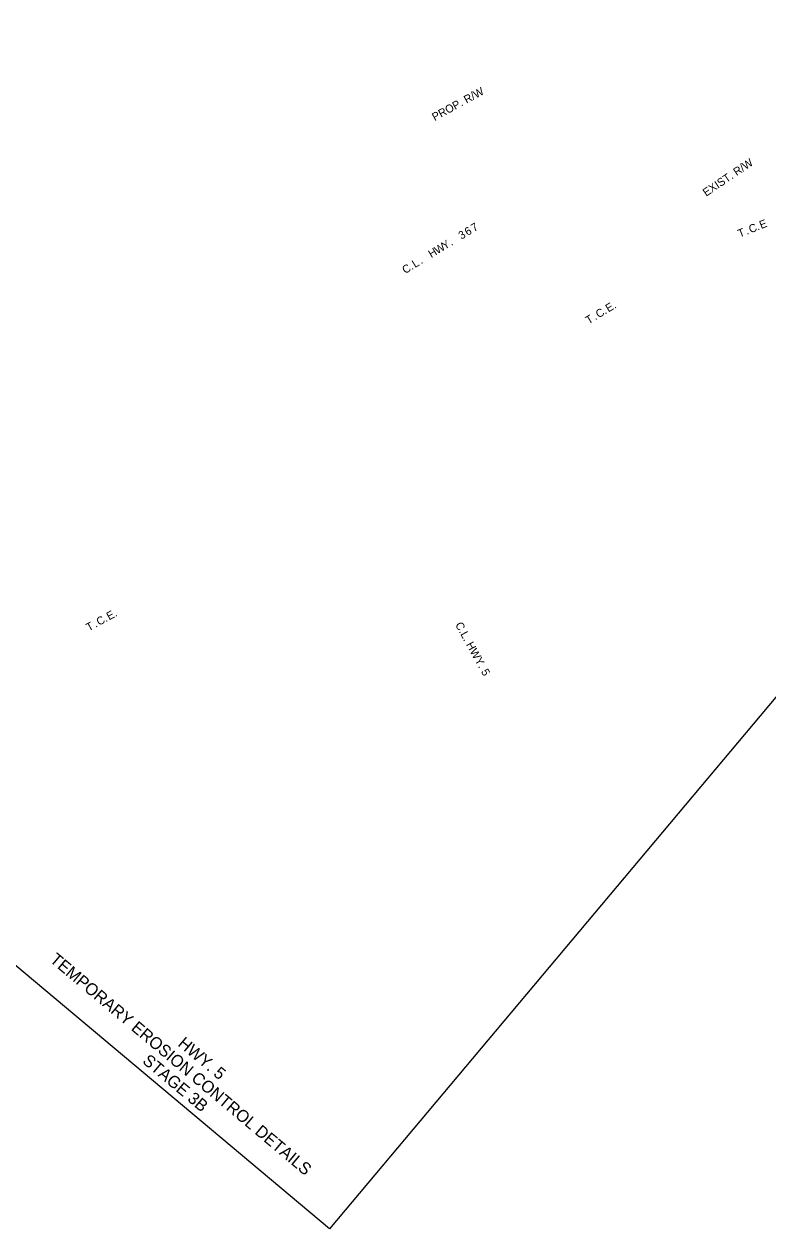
# Model space of a CAD drawing. Extents: x 1292584 to 1294692, y 222754 to 224578.
# Drawn here: x 1293577 to 1294135, y 222754 to 223658 of the extents above; entities that cross this region are included whole.
import ezdxf

# ---------------------------------------------------------------- set-up
doc = ezdxf.new("R2010")
doc.units = 0
for name, color, linetype in [('S_FIBER_OPTIC_CABLE_ANNOT', 7, 'Continuous'), ('S_MISC_TOPO_POINT', 7, 'Continuous'), ('S_SHOULDER', 7, 'Continuous'), ('S_STORM_SEWER_ANNOT', 7, 'Continuous')]:
    doc.layers.add(name, color=color, linetype=linetype)

msp = doc.modelspace()

# ---------------------------------------------------------------- linework, layer by layer
at = {"layer": 'S_SHOULDER'}
msp.add_lwpolyline([(1292584.05, 223779.83), (1293254.04, 224578.3), (1294171.77, 223808.23), (1294139.92, 223770.28), (1294291.79, 223642.84), (1294281.83, 223630.97), (1294336.68, 223584.95), (1294241.87, 223471.95), (1294339.54, 223390), (1293806.17, 222754.35)], close=True, dxfattribs=at)
msp.add_lwpolyline([(1292584.05, 223779.83), (1293254.04, 224578.3), (1294171.77, 223808.23), (1294139.92, 223770.28), (1294291.79, 223642.84), (1294281.83, 223630.97), (1294336.68, 223584.95), (1294241.87, 223471.95), (1294339.54, 223390), (1293806.17, 222754.35)], close=True, dxfattribs=at)
msp.add_lwpolyline([(1292584.05, 223779.83), (1293254.04, 224578.3), (1294171.77, 223808.23), (1294139.92, 223770.28), (1294291.79, 223642.84), (1294281.83, 223630.97), (1294336.68, 223584.95), (1294241.87, 223471.95), (1294339.54, 223390), (1293806.17, 222754.35)], close=True, dxfattribs=at)
msp.add_lwpolyline([(1292584.05, 223779.83), (1293254.04, 224578.3), (1294171.77, 223808.23), (1294139.92, 223770.28), (1294291.79, 223642.84), (1294281.83, 223630.97), (1294336.68, 223584.95), (1294241.87, 223471.95), (1294339.54, 223390), (1293806.17, 222754.35)], close=True, dxfattribs=at)
msp.add_lwpolyline([(1292584.05, 223779.83), (1293254.04, 224578.3), (1294171.77, 223808.23), (1294139.92, 223770.28), (1294291.79, 223642.84), (1294281.83, 223630.97), (1294336.68, 223584.95), (1294241.87, 223471.95), (1294339.54, 223390), (1293806.17, 222754.35)], close=True, dxfattribs=at)
msp.add_lwpolyline([(1292584.05, 223779.83), (1293254.04, 224578.3), (1294171.77, 223808.23), (1294139.92, 223770.28), (1294291.79, 223642.84), (1294281.83, 223630.97), (1294336.68, 223584.95), (1294241.87, 223471.95), (1294339.54, 223390), (1293806.17, 222754.35)], close=True, dxfattribs=at)

# ---------------------------------------------------------------- texts
at = {"layer": 'S_FIBER_OPTIC_CABLE_ANNOT'}
for s, rotation, p in [('PROP. R/W', 28.60191, (1293885.01, 223585.14)), ('EXIST. R/W', 34.11752, (1294088.57, 223528.38))]:
    msp.add_text(s, height=6, rotation=rotation, dxfattribs=at).set_placement(p)
at = {"layer": 'S_MISC_TOPO_POINT'}
for s, p in [('TEMPORARY EROSION CONTROL DETAILS', (1293595.79, 222955.14)), ('HWY. 5', (1293691.82, 222892.19)), ('STAGE 3B', (1293665.21, 222879.27))]:
    msp.add_text(s, height=9, rotation=320, dxfattribs=at).set_placement(p)
at = {"layer": 'S_STORM_SEWER_ANNOT'}
for s, rotation, p in [('7', 31.13376, (1293914.49, 223501.89)), ('C', 21.6622, (1294121.89, 223501)), ('E', 21.6622, (1294129.88, 223504.17)), ('3', 31.24435, (1293905.05, 223496.17)), ('6', 31.19047, (1293909.65, 223498.96)), ('T', 21.6622, (1294113.72, 223497.75)), ('.', 21.6622, (1294119.17, 223499.91)), ('.', 21.6622, (1294127.16, 223503.09)), ('H', 31.49372, (1293882.45, 223482.37)), ('W', 31.45559, (1293887.04, 223485.18)), ('Y', 31.39132, (1293892.51, 223488.53)), ('.', 31.33367, (1293897.43, 223491.53)), ('L', 31.49372, (1293870.24, 223474.89)), ('C', 31.49372, (1293862.91, 223470.4)), ('.', 31.49372, (1293867.74, 223473.36)), ('.', 31.49372, (1293874.83, 223477.71)), ('C', 30.9348, (1294007.92, 223437.19)), ('E', 30.9348, (1294015.29, 223441.61)), ('.', 30.9348, (1294019.91, 223444.38)), ('T', 30.9348, (1294000.38, 223432.68)), ('.', 30.9348, (1294005.41, 223435.69)), ('.', 30.9348, (1294012.78, 223440.11)), ('E', 28.53219, (1293640.87, 223210.68)), ('T', 28.53219, (1293625.59, 223202.37)), ('C', 28.53219, (1293633.32, 223206.57)), ('.', 28.53219, (1293638.3, 223209.28)), ('.', 28.53219, (1293645.6, 223213.25)), ('C.L. HWY. 5', 298.77322, (1293900.19, 223207.5)), ('.', 28.53219, (1293630.74, 223205.17))]:
    msp.add_text(s, height=6, rotation=rotation, dxfattribs=at).set_placement(p)

doc.saveas('drawing.dxf')
